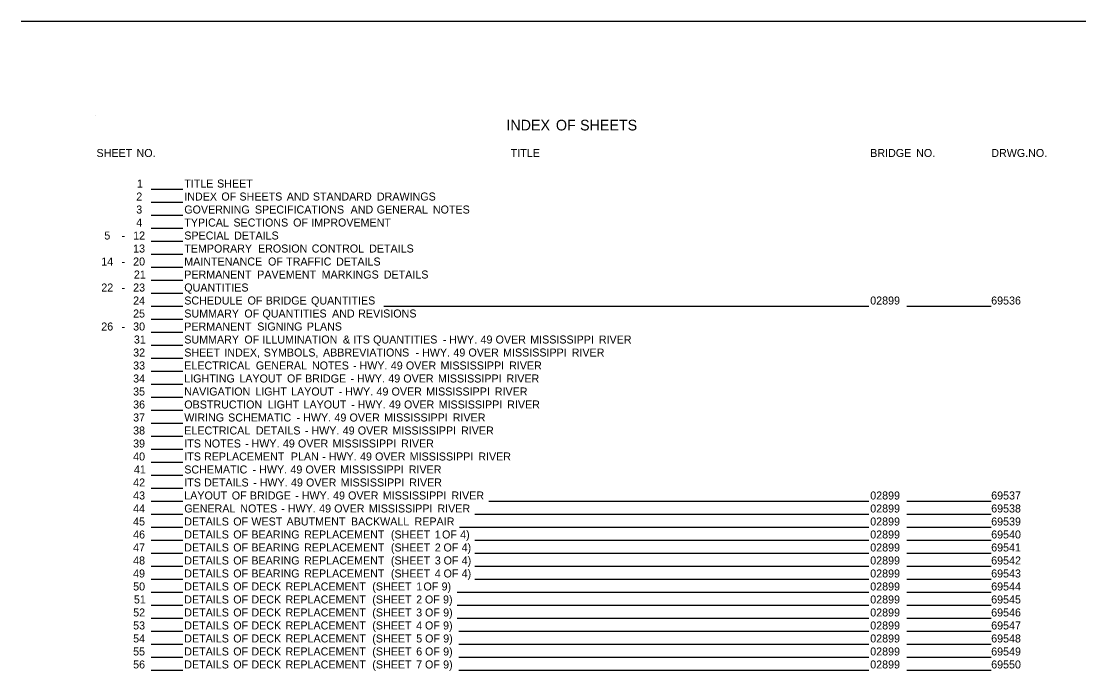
# Model space of a CAD drawing. Extents: x 76 to 3247, y 35 to 1167.
# Drawn here: x 76 to 869, y 584 to 1071 of the extents above; entities that cross this region are included whole.
import ezdxf

# ---------------------------------------------------------------- set-up
doc = ezdxf.new("R2010")
doc.units = 0
doc.layers.add('Default', color=7, linetype='Continuous')

msp = doc.modelspace()

# ---------------------------------------------------------------- linework, layer by layer
at = {"layer": 'Default'}
for p, q in [((75.8, 1071.16), (1671.16, 1071.16)), ((131.32, 1000.73), (131.32, 1000.73)), ((173.25, 945.15), (197.14, 945.15)), ((173.25, 935.4), (197.14, 935.4)), ((173.25, 925.65), (197.14, 925.65)), ((173.25, 915.9), (197.14, 915.9)), ((173.25, 906.15), (197.14, 906.15)), ((173.25, 896.4), (197.14, 896.4)), ((173.25, 886.65), (197.14, 886.65)), ((173.25, 876.9), (197.14, 876.9)), ((173.25, 867.15), (197.14, 867.15)), ((173.25, 857.4), (197.14, 857.4)), ((347.66, 857.4), (711.45, 857.4)), ((739.88, 857.4), (803.19, 857.4)), ((173.25, 847.65), (197.14, 847.65)), ((173.25, 837.9), (197.14, 837.9)), ((173.25, 828.15), (197.14, 828.15)), ((173.25, 818.4), (197.14, 818.4)), ((173.25, 808.65), (197.14, 808.65)), ((173.25, 798.9), (197.14, 798.9)), ((173.25, 789.15), (197.14, 789.15)), ((173.25, 779.4), (197.14, 779.4)), ((173.25, 769.65), (197.14, 769.65)), ((173.25, 759.9), (197.14, 759.9)), ((173.25, 750.15), (197.14, 750.15)), ((173.25, 740.4), (197.14, 740.4)), ((173.25, 730.65), (197.14, 730.65)), ((173.25, 720.9), (197.14, 720.9)), ((173.25, 711.15), (197.14, 711.15)), ((426.35, 711.15), (711.45, 711.15)), ((739.88, 711.15), (803.19, 711.15)), ((173.25, 701.4), (197.14, 701.4)), ((416.05, 701.4), (711.45, 701.4)), ((739.88, 701.4), (803.19, 701.4)), ((173.25, 691.65), (197.14, 691.65)), ((404.36, 691.65), (711.45, 691.65)), ((739.88, 691.65), (803.19, 691.65)), ((173.25, 681.9), (197.14, 681.9)), ((416.05, 681.9), (711.45, 681.9)), ((739.88, 681.9), (803.19, 681.9)), ((173.25, 672.15), (197.14, 672.15)), ((416.05, 672.15), (711.45, 672.15)), ((739.88, 672.15), (803.19, 672.15)), ((173.25, 662.4), (197.14, 662.4)), ((416.05, 662.4), (711.45, 662.4)), ((739.88, 662.4), (803.19, 662.4)), ((173.25, 652.65), (197.14, 652.65)), ((416.05, 652.65), (711.45, 652.65)), ((739.88, 652.65), (803.19, 652.65)), ((173.25, 642.9), (197.14, 642.9)), ((402.8, 642.9), (711.45, 642.9)), ((739.88, 642.9), (803.19, 642.9)), ((173.25, 633.15), (197.14, 633.15)), ((402.8, 633.15), (711.45, 633.15)), ((739.88, 633.15), (803.19, 633.15)), ((173.25, 623.4), (197.14, 623.4)), ((402.8, 623.4), (711.45, 623.4)), ((739.88, 623.4), (803.19, 623.4)), ((173.25, 613.65), (197.14, 613.65)), ((403.9, 613.65), (711.45, 613.65)), ((739.88, 613.65), (803.19, 613.65)), ((173.25, 603.9), (197.14, 603.9)), ((403.97, 603.9), (711.45, 603.9)), ((739.88, 603.9), (803.19, 603.9)), ((173.25, 594.15), (197.14, 594.15)), ((403.94, 594.15), (711.45, 594.15)), ((739.88, 594.15), (803.19, 594.15)), ((173.25, 584.4), (197.14, 584.4)), ((404.01, 584.4), (711.45, 584.4)), ((739.88, 584.4), (803.19, 584.4))]:
    msp.add_line(p, q, dxfattribs=at)

# ---------------------------------------------------------------- texts
for s, height, p in [('INDEX', 8, (439.62, 989.16)), (' OF', 8, (473.77, 989.16)), (' SHEETS', 8, (491.88, 989.16)), ('SHEET', 6, (132.3, 969.26)), (' NO.', 6, (160.08, 969.26)), ('TITLE', 6, (442.86, 969.26)), ('BRIDGE', 6, (712.42, 969.26)), (' NO.', 6, (744.61, 969.26)), ('DRWG.NO.', 6, (803.19, 969.26)), ('1', 6, (162.67, 946.35)), ('TITLE', 6, (198.11, 946.35)), (' SHEET', 6, (220.49, 946.35)), ('2', 6, (162.12, 936.6)), ('INDEX', 6, (198.11, 936.6)), (' OF', 6, (223.68, 936.6)), (' SHEETS', 6, (237.27, 936.6)), (' AND', 6, (272.7, 936.6)), (' STANDARD', 6, (292.29, 936.6)), (' DRAWINGS', 6, (340.29, 936.6)), ('3', 6, (162.09, 926.85)), ('GOVERNING', 6, (198.11, 926.85)), (' SPECIFICATIONS', 6, (248.83, 926.85)), (' AND', 6, (320.59, 926.85)), (' GENERAL', 6, (340.18, 926.85)), (' NOTES', 6, (382.28, 926.85)), ('4', 6, (162.1, 917.1)), ('TYPICAL', 6, (198.11, 917.1)), (' SECTIONS', 6, (232.76, 917.1)), (' OF', 6, (277.51, 917.1)), (' IMPROVEMENT', 6, (291.09, 917.1)), ('5', 6, (138.18, 907.35)), ('12', 6, (159.79, 907.35)), ('SPECIAL', 6, (198.11, 907.35)), (' DETAILS', 6, (233.23, 907.35)), ('-', 6, (151.02, 907.35)), ('13', 6, (159.76, 897.6)), ('TEMPORARY', 6, (198.11, 897.6)), (' EROSION', 6, (251.15, 897.6)), (' CONTROL', 6, (291.46, 897.6)), (' DETAILS', 6, (334.48, 897.6)), ('14', 6, (135.89, 887.85)), ('-', 6, (151.02, 887.85)), ('20', 6, (159.77, 887.85)), ('MAINTENANCE', 6, (198.11, 887.85)), (' OF', 6, (258.69, 887.85)), (' TRAFFIC', 6, (272.27, 887.85)), (' DETAILS', 6, (309.66, 887.85)), ('21', 6, (160.34, 878.1)), ('PERMANENT', 6, (198.11, 878.1)), (' PAVEMENT', 6, (250.58, 878.1)), (' MARKINGS', 6, (298.87, 878.1)), (' DETAILS', 6, (345.48, 878.1)), ('22', 6, (135.9, 868.35)), ('23', 6, (159.76, 868.35)), ('QUANTITIES', 6, (198.11, 868.35)), ('-', 6, (151.02, 868.35)), ('24', 6, (159.77, 858.6)), ('SCHEDULE', 6, (198.11, 858.6)), (' OF', 6, (243.32, 858.6)), (' BRIDGE', 6, (256.91, 858.6)), (' QUANTITIES', 6, (290.93, 858.6)), ('02899', 6, (712.42, 858.6)), ('69536', 6, (803.1, 858.6)), ('25', 6, (159.74, 848.85)), ('SUMMARY', 6, (198.11, 848.85)), (' OF', 6, (240.9, 848.85)), (' QUANTITIES', 6, (254.49, 848.85)), (' AND', 6, (306.69, 848.85)), (' REVISIONS', 6, (326.27, 848.85)), ('26', 6, (135.87, 839.1)), ('-', 6, (151.02, 839.1)), ('30', 6, (159.77, 839.1)), ('PERMANENT', 6, (198.11, 839.1)), (' SIGNING', 6, (250.58, 839.1)), (' PLANS', 6, (287.79, 839.1)), ('31', 6, (160.34, 829.35)), ('SUMMARY', 6, (198.11, 829.35)), (' OF', 6, (240.9, 829.35)), (' ILLUMINATION', 6, (254.49, 829.35)), (' &', 6, (314.82, 829.35)), (' ITS', 6, (322.55, 829.35)), (' QUANTITIES', 6, (337.48, 829.35)), (' HWY.', 6, (394.53, 829.35)), (' 49', 6, (418.02, 829.35)), (' OVER', 6, (429.29, 829.35)), (' MISSISSIPPI', 6, (455.27, 829.35)), (' RIVER', 6, (506.7, 829.35)), ('32', 6, (159.79, 819.6)), ('SHEET', 6, (198.11, 819.6)), (' INDEX,', 6, (225.9, 819.6)), (' SYMBOLS,', 6, (255.43, 819.6)), (' ABBREVIATIONS', 6, (299.88, 819.6)), (' HWY.', 6, (374.18, 819.6)), (' -', 6, (389.68, 829.35)), (' 49', 6, (397.67, 819.6)), (' OVER', 6, (408.94, 819.6)), (' MISSISSIPPI', 6, (434.92, 819.6)), (' RIVER', 6, (486.35, 819.6)), (' -', 6, (369.33, 819.6)), ('33', 6, (159.76, 809.85)), ('ELECTRICAL', 6, (198.11, 809.85)), (' GENERAL', 6, (249.53, 809.85)), (' NOTES', 6, (291.63, 809.85)), (' -', 6, (322.4, 809.85)), (' HWY.', 6, (327.26, 809.85)), (' 49', 6, (350.74, 809.85)), (' OVER', 6, (362.02, 809.85)), (' MISSISSIPPI', 6, (387.99, 809.85)), (' RIVER', 6, (439.42, 809.85)), ('34', 6, (159.77, 800.1)), ('LIGHTING', 6, (198.11, 800.1)), (' LAYOUT', 6, (237.17, 800.1)), (' OF', 6, (272.88, 800.1)), (' BRIDGE', 6, (286.46, 800.1)), (' -', 6, (320.49, 800.1)), (' HWY.', 6, (325.35, 800.1)), (' 49', 6, (348.83, 800.1)), (' OVER', 6, (360.11, 800.1)), (' MISSISSIPPI', 6, (386.08, 800.1)), (' RIVER', 6, (437.51, 800.1)), ('35', 6, (159.74, 790.35)), ('NAVIGATION', 6, (198.11, 790.35)), (' LIGHT', 6, (249.13, 790.35)), (' LAYOUT', 6, (275.98, 790.35)), (' HWY.', 6, (316.54, 790.35)), (' 49', 6, (340.02, 790.35)), (' OVER', 6, (351.3, 790.35)), (' MISSISSIPPI', 6, (377.27, 790.35)), (' RIVER', 6, (428.7, 790.35)), ('36', 6, (159.76, 780.6)), ('OBSTRUCTION', 6, (198.11, 780.6)), (' LIGHT', 6, (258.44, 780.6)), (' LAYOUT', 6, (285.29, 780.6)), (' -', 6, (311.68, 790.35)), (' HWY.', 6, (325.85, 780.6)), (' 49', 6, (349.33, 780.6)), (' OVER', 6, (360.61, 780.6)), (' MISSISSIPPI', 6, (386.58, 780.6)), (' RIVER', 6, (438.01, 780.6)), (' -', 6, (320.99, 780.6)), ('37', 6, (159.76, 770.85)), ('WIRING', 6, (198.11, 770.85)), (' SCHEMATIC', 6, (228.78, 770.85)), (' -', 6, (280.15, 770.85)), (' HWY.', 6, (285.01, 770.85)), (' 49', 6, (308.49, 770.85)), (' OVER', 6, (319.77, 770.85)), (' MISSISSIPPI', 6, (345.75, 770.85)), (' RIVER', 6, (397.18, 770.85)), ('38', 6, (159.75, 761.1)), ('ELECTRICAL', 6, (198.11, 761.1)), (' DETAILS', 6, (249.53, 761.1)), (' -', 6, (286.36, 761.1)), (' HWY.', 6, (291.22, 761.1)), (' 49', 6, (314.7, 761.1)), (' OVER', 6, (325.98, 761.1)), (' MISSISSIPPI', 6, (351.95, 761.1)), (' RIVER', 6, (403.38, 761.1)), ('39', 6, (159.75, 751.35)), ('ITS', 6, (198.11, 751.35)), (' NOTES', 6, (210.71, 751.35)), (' -', 6, (241.49, 751.35)), (' HWY.', 6, (246.34, 751.35)), (' 49', 6, (269.83, 751.35)), (' OVER', 6, (281.1, 751.35)), (' MISSISSIPPI', 6, (307.08, 751.35)), (' RIVER', 6, (358.51, 751.35)), ('40', 6, (159.77, 741.6)), ('ITS', 6, (198.11, 741.6)), (' REPLACEMENT', 6, (210.71, 741.6)), (' PLAN', 6, (275.77, 741.6)), (' HWY.', 6, (304.17, 741.6)), (' 49', 6, (327.65, 741.6)), (' OVER', 6, (338.93, 741.6)), (' MISSISSIPPI', 6, (364.9, 741.6)), (' RIVER', 6, (416.33, 741.6)), ('41', 6, (160.34, 731.85)), ('SCHEMATIC', 6, (198.11, 731.85)), (' HWY.', 6, (252.01, 731.85)), (' 49', 6, (275.49, 731.85)), (' OVER', 6, (286.77, 731.85)), (' -', 6, (299.31, 741.6)), (' MISSISSIPPI', 6, (312.75, 731.85)), (' RIVER', 6, (364.18, 731.85)), (' -', 6, (247.15, 731.85)), ('42', 6, (159.79, 722.1)), ('ITS', 6, (198.11, 722.1)), (' DETAILS', 6, (210.71, 722.1)), (' -', 6, (247.55, 722.1)), (' HWY.', 6, (252.4, 722.1)), (' 49', 6, (275.89, 722.1)), (' OVER', 6, (287.16, 722.1)), (' MISSISSIPPI', 6, (313.14, 722.1)), (' RIVER', 6, (364.57, 722.1)), ('43', 6, (159.76, 712.35)), ('LAYOUT', 6, (198.11, 712.35)), (' OF', 6, (231.49, 712.35)), (' BRIDGE', 6, (245.07, 712.35)), (' -', 6, (279.1, 712.35)), (' HWY.', 6, (283.95, 712.35)), (' 49', 6, (307.44, 712.35)), (' OVER', 6, (318.71, 712.35)), (' MISSISSIPPI', 6, (344.69, 712.35)), (' RIVER', 6, (396.12, 712.35)), ('02899', 6, (712.42, 712.35)), ('69537', 6, (803.1, 712.35)), ('44', 6, (159.77, 702.6)), ('GENERAL', 6, (198.11, 702.6)), (' NOTES', 6, (237.88, 702.6)), (' HWY.', 6, (273.51, 702.6)), (' 49', 6, (297, 702.6)), (' OVER', 6, (308.27, 702.6)), (' MISSISSIPPI', 6, (334.25, 702.6)), (' RIVER', 6, (385.68, 702.6)), ('02899', 6, (712.42, 702.6)), ('69538', 6, (803.1, 702.6)), ('45', 6, (159.74, 692.85)), ('DETAILS', 6, (198.11, 692.85)), (' OF', 6, (232.61, 692.85)), (' WEST', 6, (246.2, 692.85)), (' -', 6, (268.66, 702.6)), (' ABUTMENT', 6, (272.58, 692.85)), (' BACKWALL', 6, (320.85, 692.85)), (' REPAIR', 6, (368.54, 692.85)), ('02899', 6, (712.42, 692.85)), ('69539', 6, (803.1, 692.85)), ('46', 6, (159.76, 683.1)), ('DETAILS', 6, (198.11, 683.1)), (' OF', 6, (232.61, 683.1)), (' BEARING', 6, (246.2, 683.1)), (' REPLACEMENT', 6, (285.74, 683.1)), (' (SHEET', 6, (350.79, 683.1)), (' 1', 6, (383.7, 683.1)), (' OF', 6, (389.15, 683.1)), (' 4)', 6, (402.73, 683.1)), ('02899', 6, (712.42, 683.1)), ('69540', 6, (803.1, 683.1)), ('47', 6, (159.76, 673.35)), ('DETAILS', 6, (198.11, 673.35)), (' OF', 6, (232.61, 673.35)), (' BEARING', 6, (246.2, 673.35)), (' REPLACEMENT', 6, (285.74, 673.35)), (' (SHEET', 6, (350.79, 673.35)), (' 2', 6, (383.7, 673.35)), (' OF', 6, (390.24, 673.35)), (' 4)', 6, (403.83, 673.35)), ('02899', 6, (712.42, 673.35)), ('69541', 6, (803.1, 673.35)), ('48', 6, (159.75, 663.6)), ('DETAILS', 6, (198.11, 663.6)), (' OF', 6, (232.61, 663.6)), (' BEARING', 6, (246.2, 663.6)), (' REPLACEMENT', 6, (285.74, 663.6)), (' (SHEET', 6, (350.79, 663.6)), (' 3', 6, (383.7, 663.6)), (' OF', 6, (390.31, 663.6)), (' 4)', 6, (403.89, 663.6)), ('02899', 6, (712.42, 663.6)), ('69542', 6, (803.1, 663.6)), ('49', 6, (159.75, 653.85)), ('DETAILS', 6, (198.11, 653.85)), (' OF', 6, (232.61, 653.85)), (' BEARING', 6, (246.2, 653.85)), (' REPLACEMENT', 6, (285.74, 653.85)), (' (SHEET', 6, (350.79, 653.85)), (' 4', 6, (383.7, 653.85)), (' OF', 6, (390.28, 653.85)), (' 4)', 6, (403.87, 653.85)), ('02899', 6, (712.42, 653.85)), ('69543', 6, (803.1, 653.85)), (' (SHEET', 6, (336.86, 644.1)), (' 9)', 6, (388.8, 644.1)), ('50', 6, (159.77, 644.1)), ('DETAILS', 6, (198.11, 644.1)), (' OF', 6, (232.61, 644.1)), (' DECK', 6, (246.2, 644.1)), (' REPLACEMENT', 6, (271.81, 644.1)), (' 1', 6, (369.76, 644.1)), (' OF', 6, (375.21, 644.1)), ('02899', 6, (712.42, 644.1)), ('69544', 6, (803.1, 644.1)), ('51', 6, (160.34, 634.35)), ('DETAILS', 6, (198.11, 634.35)), (' OF', 6, (232.61, 634.35)), (' DECK', 6, (246.2, 634.35)), (' REPLACEMENT', 6, (271.81, 634.35)), (' (SHEET', 6, (336.86, 634.35)), (' 2', 6, (369.76, 634.35)), (' OF', 6, (376.31, 634.35)), (' 9)', 6, (389.9, 634.35)), ('02899', 6, (712.42, 634.35)), ('69545', 6, (803.1, 634.35)), ('52', 6, (159.79, 624.6)), ('DETAILS', 6, (198.11, 624.6)), (' OF', 6, (232.61, 624.6)), (' DECK', 6, (246.2, 624.6)), (' REPLACEMENT', 6, (271.81, 624.6)), (' (SHEET', 6, (336.86, 624.6)), (' 3', 6, (369.76, 624.6)), (' OF', 6, (376.37, 624.6)), (' 9)', 6, (389.96, 624.6)), ('02899', 6, (712.42, 624.6)), ('69546', 6, (803.1, 624.6)), ('53', 6, (159.76, 614.85)), ('DETAILS', 6, (198.11, 614.85)), (' OF', 6, (232.61, 614.85)), (' DECK', 6, (246.2, 614.85)), (' REPLACEMENT', 6, (271.81, 614.85)), (' (SHEET', 6, (336.86, 614.85)), (' 4', 6, (369.76, 614.85)), (' OF', 6, (376.35, 614.85)), (' 9)', 6, (389.93, 614.85)), ('02899', 6, (712.42, 614.85)), ('69547', 6, (803.1, 614.85)), ('54', 6, (159.77, 605.1)), ('DETAILS', 6, (198.11, 605.1)), (' OF', 6, (232.61, 605.1)), (' DECK', 6, (246.2, 605.1)), (' REPLACEMENT', 6, (271.81, 605.1)), (' (SHEET', 6, (336.86, 605.1)), (' 5', 6, (369.76, 605.1)), (' OF', 6, (376.42, 605.1)), (' 9)', 6, (390.01, 605.1)), ('02899', 6, (712.42, 605.1)), ('69548', 6, (803.1, 605.1)), ('55', 6, (159.74, 595.35)), ('DETAILS', 6, (198.11, 595.35)), (' OF', 6, (232.61, 595.35)), (' DECK', 6, (246.2, 595.35)), (' REPLACEMENT', 6, (271.81, 595.35)), (' (SHEET', 6, (336.86, 595.35)), (' 6', 6, (369.76, 595.35)), (' OF', 6, (376.37, 595.35)), (' 9)', 6, (389.96, 595.35)), ('02899', 6, (712.42, 595.35)), ('69549', 6, (803.1, 595.35)), ('56', 6, (159.76, 585.6)), ('DETAILS', 6, (198.11, 585.6)), (' OF', 6, (232.61, 585.6)), (' DECK', 6, (246.2, 585.6)), (' REPLACEMENT', 6, (271.81, 585.6)), (' (SHEET', 6, (336.86, 585.6)), (' 7', 6, (369.76, 585.6)), (' OF', 6, (376.37, 585.6)), (' 9)', 6, (389.96, 585.6)), ('02899', 6, (712.42, 585.6)), ('69550', 6, (803.1, 585.6))]:
    msp.add_text(s, height=height, dxfattribs=at).set_placement(p)

doc.saveas('drawing.dxf')
